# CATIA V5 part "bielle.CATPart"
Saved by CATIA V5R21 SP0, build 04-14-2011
Part number: bielle
Nomenclature: EP-01
Material "Gris bleu": density 7860 kg/m3, Young's modulus 2e+11 Pa, Poisson ratio 0.266
Bounding box of the stored display mesh (mm): x -4.5 to 4.5, y -3.5 to 3.5, z -20.75 to 20.75
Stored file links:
  C:\Users\Utilisateur\Desktop\2015.02.10 Sauvegarde - redaction CATIA (local)\CATIA\DONNEES\Exercice mise en plan 1 (bielle)\bielle.CATPart
  C:\Program Files\Dassault Systemes\B21\win_b64\startup\materials\French\Catalog.CATMaterial
  C:\Users\Utilisateur\Desktop\2015.02.10 Sauvegarde - redaction CATIA (local)\pompe à moteur de ventilation refait\Pompe_a_moteur_de_ventilation.CATProduct
  C:\Users\Utilisateur\Desktop\2015.02.10 Sauvegarde - redaction CATIA (local)\pompe à moteur de ventilation refait\Ecrou a collerette M5.CATPart
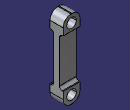
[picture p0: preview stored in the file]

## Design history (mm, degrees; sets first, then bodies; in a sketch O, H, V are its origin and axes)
Body1 (main body), material "Gris bleu"
  Sketch1 on yz-plane, origin (0, 0, 0), H (0, 1, 0), V (0, 0, 1)
    line L1 (3.5, 20.75) -> (3.5, 12.75)
    line L2 (3.5, -20.75) -> (-3.5, -20.75)
    line L3 (-3.5, -20.75) -> (-3.5, -12.75)
    line L4 (-3.5, 20.75) -> (3.5, 20.75)
    point P1 (3.5, 20.75)
    point P2 (3.5, -20.75)
    point P5 (3.5, 12.75)
    point P6 (-3.5, 12.75)
    point P7 (-3.5, -12.75)
    point P8 (3.5, -12.75)
    line L5 (1.5, 12.75) -> (1.5, -12.75)
    point P9 (1.5, 12.75)
    point P10 (1.5, -12.75)
    point P11 (-1.5, -12.75)
    point P12 (-1.5, 12.75)
    line L6 (-1.5, 12.75) -> (-1.5, -12.75)
    line L7 (3.5, -12.75) -> (3.5, -20.75)
    line L8 (-3.5, 12.75) -> (-3.5, 20.75)
    point P13 (1.5, 12.75)
    point P14 (-1.5, 12.75)
    point P15 (-1.5, -12.75)
    point P16 (1.5, -12.75)
    line L9 (3.5, 12.75) -> (1.5, 12.75)
    point P17 (1.5, 12.75)
    line L10 (-3.5, 12.75) -> (-1.5, 12.75)
    point P18 (-1.5, 12.75)
    line L11 (-3.5, -12.75) -> (-1.5, -12.75)
    point P19 (-1.5, -12.75)
    line L12 (3.5, -12.75) -> (1.5, -12.75)
    point P20 (1.5, -12.75)
    length L4 = 7
    distance L5 V = 1.5
    distance P1 P2 = 41.5
    length L1 = 8
    length L3 = 8
    vertical: L1 V, L3 V, L5 V, L7 V, L8 V
    horizontal: L2 H, L4 H, L9 H, L10 H, L11 H, L12 H
    equidistance: L1 L3 O, L2 L4 O
    coincidence: P6 L3, L1 L7, L3 L8, L5 P9, L6 P12, L6 P11, L5 P10, P14 P12, P13 P9, P17 L5, P18 L6, P12 P18, P11 P15, P16 P10, P19 L6, P20 L5, P11 P19
    symmetry: P6 P7 H, P5 P8 H, P10 P11 V, P9 P12 V, L5 L6 V
  Pad1: profile Sketch1, direction (1, 0, 0), length 4.5, mirrored extent
  Sketch2 on zx-plane, origin (0, 0, 0), H (-1, 0, 0), V (0, 0, 1)
    circle A1 centre (0, 16.5) radius 2.5
    point P1 (0, 16.5)
    circle A2 centre (0, -16.5) radius 2.5
    distance P1 H = 16.5
    coincidence: P1 V
    symmetry: A1 A2 H
  Pocket1: profile Sketch2, direction (0, -1, 0), length 4.5, mirrored extent
  Fillet1: radius 4.25, on edge [start face of Pad1 | face of Pad1 from Sketch1.L2]; edge [face of Pad1 from Sketch1.L2 | end face of Pad1]; edge [start face of Pad1 | face of Pad1 from Sketch1.L4]; edge [face of Pad1 from Sketch1.L4 | end face of Pad1]
  Fillet2: radius 1.5, on edge [face of Pad1 from Sketch1.L9 | face of Pad1 from Sketch1.L5]; edge [face of Pad1 from Sketch1.L5 | face of Pad1 from Sketch1.L12]; edge [face of Pad1 from Sketch1.L11 | face of Pad1 from Sketch1.L6]; edge [face of Pad1 from Sketch1.L6 | face of Pad1 from Sketch1.L10]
